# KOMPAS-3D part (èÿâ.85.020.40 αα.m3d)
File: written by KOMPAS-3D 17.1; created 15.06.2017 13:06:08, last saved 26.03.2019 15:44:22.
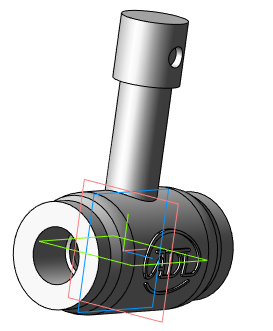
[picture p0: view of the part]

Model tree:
1. Операция без истории:3  (labels: Сталь 20  ГОСТ 1050-88)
